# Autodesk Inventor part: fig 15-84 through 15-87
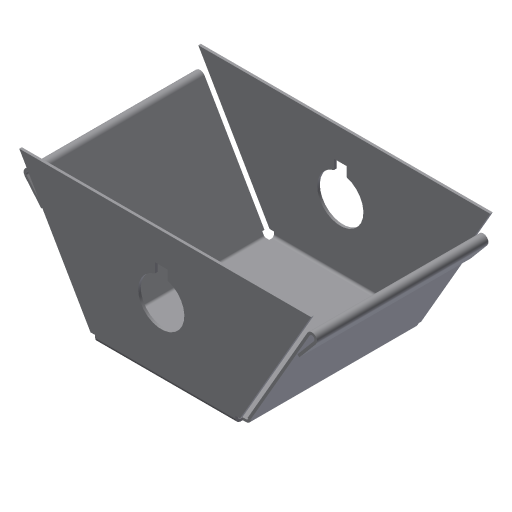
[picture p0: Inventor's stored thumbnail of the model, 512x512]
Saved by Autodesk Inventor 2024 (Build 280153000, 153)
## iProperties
Shininess: 50.0
Angle Display Precision: 2
Document Length Units: 11269
Document Angle Units: 11279
Document Time Units: 11290
Document Mass Units: 11283
Document Length Units Precision: 3
Document Angle Units Precision: 2
Created: 2002-04
Part Number: fig 15-84 through 15-87
Document SubType Name: Sheet Metal
Density: 1 g/cm^3
Sheet Metal Rule: Default
Material: Generic
Appearance: Default
Density: 0.0
Volumn: 0.0
Area: 0.0
PropertySet Name: Model Information
Control State: 0
Master: False
Checked Out: False
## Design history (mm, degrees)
node "Face1"
  sketch "Sketch1"
    geometry: L1 (-24.824, 17.882)-(5.529, 17.882); L2 (5.529, 17.882)-(5.529, -17.529); L3 (5.529, -17.529)-(-24.824, -17.529); L4 (-24.824, -17.529)-(-24.824, 17.882)
    constraints: 8 end point, 2 parallel, 1 horizontal, 1 perpendicular
node "Flange2"
node "Flange3"
node "Flange4"
node "Flange5"
feature "Corner1" dims "d45" = 0.5 (= Thickness), "d46" = 0, "d81" = 2 (= CornerReliefSize), "d85" = 0.5 (= Thickness), "TransitionRadius" = 0.5 (= BendRadius)
feature "Corner2" dims "d47" = 0.5 (= Thickness), "d48" = 0, "d82" = 2 (= CornerReliefSize), "d85" = 0.5 (= Thickness), "TransitionRadius" = 0.5 (= BendRadius)
feature "Corner3" dims "d49" = 0.5 (= Thickness), "d50" = 0, "d83" = 2 (= CornerReliefSize), "d85" = 0.5 (= Thickness), "TransitionRadius" = 0.5 (= BendRadius)
feature "Corner4" dims "d51" = 0.5 (= Thickness), "d52" = 0, "d84" = 2 (= CornerReliefSize), "d85" = 0.5 (= Thickness), "TransitionRadius" = 0.5 (= BendRadius)
feature "Hem1" dims "d53" = 0.5 (= BendRadius), "d54" = 190 deg, "d55" = 0.5 (= BendRadius), "d56" = 0.5 (= d55), "d75" = 0.5 (= BendReliefWidth), "d76" = 0.25 (= BendReliefDepth), "d77" = 1 (= MinimumRemnant), "d85" = 0.5 (= Thickness), "SeamGap" = 0.01, "MinimumRemnant" = 1 (= 2 x Thickness), "BendReliefWidth" = 0.5 (= Thickness)
feature "Hem2" dims "d57" = 0.5 (= BendRadius), "d58" = 190 deg, "d59" = 0.5 (= BendRadius), "d60" = 0.5 (= d59), "d78" = 0.5 (= BendReliefWidth), "d79" = 0.25 (= BendReliefDepth), "d80" = 1 (= MinimumRemnant), "d85" = 0.5 (= Thickness), "SeamGap" = 0.01, "MinimumRemnant" = 1 (= 2 x Thickness), "BendReliefWidth" = 0.5 (= Thickness)
sketch "Sketch12"
  geometry: L1 (28.924, -7.829)-(28.924, -5.94); L2 (28.924, -5.94)-(26.464, -5.94); L3 (26.464, -5.94)-(26.464, -7.829); A1 r 4.497 centre (27.694, -12.155) between (26.464, -7.829) and (28.924, -7.829)
  constraints: 6 end point, 2 point on circle, 1 centre point, 1 parallel
cut "Cut1" sketch "Sketch12" dims "d61" = 0.5 (= Thickness), "d62" = 0
body "Solid1"
face "Plate1" dims "d85" = 0.5 (= Thickness)
sketch "Sketch6"
  geometry: L1 (30.412, 0)-(5, 0); L2 (5, 0)-(5, 25); L3 (5, 25)-(30.412, 25); L4 (30.412, 25)-(30.412, 0)
  constraints: 8 end point
face "Plate7" dims "d21" = 5, "d22" = 5, "d24" = 25, "d25" = 60 deg, "d26" = 0.5 (= BendRadius), "d85" = 0.5 (= Thickness), "MinimumRemnant" = 1 (= 2 x Thickness), "BendReliefWidth" = 0.5 (= Thickness)
bend "Bend6" dims "d23" = 0.5 (= BendRadius), "d24" = 25, "d25" = 60 deg, "d26" = 0.5 (= BendRadius), "d63" = 0.5 (= BendReliefWidth), "d64" = 0.25 (= BendReliefDepth), "d65" = 1 (= MinimumRemnant), "d85" = 0.5 (= Thickness), "SeamGap" = 0.01, "MinimumRemnant" = 1 (= 2 x Thickness), "BendReliefWidth" = 0.5 (= Thickness)
sketch "Sketch7"
  geometry: L1 (25.353, 0)-(5, 0); L2 (5, 0)-(5, 25); L3 (5, 25)-(25.353, 25); L4 (25.353, 25)-(25.353, 0)
  constraints: 8 end point
face "Plate8" dims "d27" = 5, "d28" = 5, "d30" = 25, "d31" = 90 deg, "d32" = 0.5 (= BendRadius), "d85" = 0.5 (= Thickness), "MinimumRemnant" = 1 (= 2 x Thickness), "BendReliefWidth" = 0.5 (= Thickness)
bend "Bend7" dims "d29" = 0.5 (= BendRadius), "d30" = 25, "d31" = 90 deg, "d32" = 0.5 (= BendRadius), "d66" = 0.5 (= BendReliefWidth), "d67" = 0.25 (= BendReliefDepth), "d68" = 1 (= MinimumRemnant), "d85" = 0.5 (= Thickness), "SeamGap" = 0.01, "MinimumRemnant" = 1 (= 2 x Thickness), "BendReliefWidth" = 0.5 (= Thickness)
sketch "Sketch8"
  geometry: L1 (5, 0)-(30.412, 0); L2 (30.412, 0)-(30.412, 25); L3 (30.412, 25)-(5, 25); L4 (5, 25)-(5, 0)
  constraints: 8 end point
face "Plate9" dims "d33" = 5, "d34" = 5, "d36" = 25, "d37" = 60 deg, "d38" = 0.5 (= BendRadius), "d85" = 0.5 (= Thickness), "MinimumRemnant" = 1 (= 2 x Thickness), "BendReliefWidth" = 0.5 (= Thickness)
bend "Bend8" dims "d35" = 0.5 (= BendRadius), "d36" = 25, "d37" = 60 deg, "d38" = 0.5 (= BendRadius), "d69" = 0.5 (= BendReliefWidth), "d70" = 0.25 (= BendReliefDepth), "d71" = 1 (= MinimumRemnant), "d85" = 0.5 (= Thickness), "SeamGap" = 0.01, "MinimumRemnant" = 1 (= 2 x Thickness), "BendReliefWidth" = 0.5 (= Thickness)
sketch "Sketch9"
  geometry: L1 (5, 0)-(25.353, 0); L2 (25.353, 0)-(25.353, 25); L3 (25.353, 25)-(5, 25); L4 (5, 25)-(5, 0)
  constraints: 8 end point
face "Plate10" dims "d39" = 5, "d40" = 5, "d42" = 25, "d43" = 90 deg, "d44" = 0.5 (= BendRadius), "d85" = 0.5 (= Thickness), "MinimumRemnant" = 1 (= 2 x Thickness), "BendReliefWidth" = 0.5 (= Thickness)
bend "Bend9" dims "d41" = 0.5 (= BendRadius), "d42" = 25, "d43" = 90 deg, "d44" = 0.5 (= BendRadius), "d72" = 0.5 (= BendReliefWidth), "d73" = 0.25 (= BendReliefDepth), "d74" = 1 (= MinimumRemnant), "d85" = 0.5 (= Thickness), "SeamGap" = 0.01, "MinimumRemnant" = 1 (= 2 x Thickness), "BendReliefWidth" = 0.5 (= Thickness)
sketch "Sketch10"
  geometry: L1 (0.433, 0.25)-(0, 0); L2 (-0.816, -0.571)-(2.395, -4.398); L3 (2.395, -4.398)-(2.012, -4.719); L4 (2.012, -4.719)-(-1.199, -0.893); A1 r 0.5 centre (-0.433, -0.25) between (0, 0) and (-0.816, -0.571); A2 r 1 centre (-0.433, -0.25) between (0.433, 0.25) and (-1.199, -0.893)
  constraints: 8 end point, 4 point on circle
sketch "Sketch11"
  geometry: L1 (0.433, 0.25)-(0, 0); L2 (-0.816, -0.571)-(2.395, -4.398); L3 (2.395, -4.398)-(2.012, -4.719); L4 (2.012, -4.719)-(-1.199, -0.893); A1 r 0.5 centre (-0.433, -0.25) between (0, 0) and (-0.816, -0.571); A2 r 1 centre (-0.433, -0.25) between (0.433, 0.25) and (-1.199, -0.893)
  constraints: 8 end point, 4 point on circle
node "FlatPattern"
feature "FlatPatternExtrusion2" dims "d0" = 0.5 (derived)
other parameters: "Thickness" = 0.5, "BendRadius" = 0.5 (= Thickness), "BendReliefDepth" = 0.25 (= 0.5 x Thickness), "CornerReliefSize" = 2 (= 4 x Thickness), "d0" = 0.5 (= BendRadius), "d4" = 0.5 (= BendRadius), "JacobiRadiusSize" = 0.5 (= Thickness), "GapSize" = 0.5 (= Thickness)
